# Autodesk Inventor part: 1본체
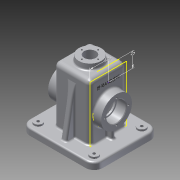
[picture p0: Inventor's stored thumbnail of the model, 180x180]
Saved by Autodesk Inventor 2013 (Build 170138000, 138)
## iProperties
Created: 2016-01
Part Number: 1본체
Material: 알루미늄 6061
Document SubType Name: Modeling
Designer: Administrator
Density: 2.71 g/cm^3
Mass: 927.953 g
Surface Area: 977.096 cm^2
Volume: 342.418 cm^3
Author: Administrator
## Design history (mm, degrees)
sketch "스케치1"
  geometry: L1 (32.5, -32.5)-(-32.5, -32.5); L2 (-32.5, -32.5)-(-32.5, 32.5); L3 (-32.5, 32.5)-(32.5, 32.5); L4 (32.5, 32.5)-(32.5, -32.5); L5 (32.5, -32.5)-(-32.5, 32.5); L6 (-32.5, -32.5)-(32.5, 32.5); 1 further point
  constraints: 12 end point, 2 midpoint, 2 parallel, 1 horizontal, 1 perpendicular
  dimensions: "d0" = 65 distance of L2.end L3.end; "d2" = 65 distance of L1.end L2.end
extrude "돌출1" new body sketch "스케치1" distance "d3" = 110; taper "d4" = 0 deg
feature "쉘1" dims "d5" = 5
sketch "스케치3"
  geometry: L1 (0, 65)-(0, 0) reference; C1 r 27.5 at (-55, 32.5); 2 further points
  constraints: 1 centre point, 1 horizontal alignment, 1 midpoint
  dimensions: "d6" = 55 diameter of C1; "d7" = 55 distance of point (0, 32.5) C1.centre
extrude "돌출2" join sketch "스케치3" distance "d8" = 15; taper "d9" = 0 deg
hole "구멍1" diameter "d12" = 30; stored, may be unused: countersink angle "d16" = 90 deg, drill point angle "d18" = 0 deg; dims "d10" = 10, "d11" = 10, "d13" = 6, "d14" = 35, "d15" = 17, "d17" = 8
sketch "스케치4"
  geometry: C1 r 17.5 at (0, 0) reference; 2 further points
  constraints: 1 horizontal alignment
  dimensions: "d19" = 21 distance of C1.centre point (-21, 0)
hole "구멍2" sketch "스케치4" at (-21, 0) diameter "d20" = 3.242; stored, may be unused: countersink angle "d24" = 90 deg, drill point angle "d26" = 118 deg; dims "d21" = 8, "d22" = 35, "d23" = 17, "d25" = 10
node "작업 평면1"
sketch "스케치5"
  geometry: C1 r 20 at (0, 0); 1 further point
  constraints: 1 centre point, 1 coincident
  dimensions: "d31" = 40 diameter of C1
extrude "돌출3" join sketch "스케치5" stored distance "d32" = 15; taper "d33" = 5 deg
sketch "스케치6"
  geometry: C1 r 20 at (0, 0) reference; C2 r 10.5 at (0, 0)
  constraints: 1 centre point, 1 coincident
  dimensions: "d34" = 21 diameter of C2
extrude "돌출4" cut sketch "스케치6" stored distance "d35" = 15; taper "d36" = 0 deg
sketch "스케치7"
  geometry: C1 r 10.5 at (0, 0) reference; 1 further point
  constraints: 1 horizontal alignment
  dimensions: "d37" = 14.5 distance of point (14.5, 0) C1.centre
hole "구멍3" sketch "스케치7" at (14.5, 0) diameter "d38" = 2.459; stored, may be unused: countersink angle "d42" = 90 deg, drill point angle "d44" = 118 deg; dims "d39" = 7, "d40" = 35, "d41" = 17, "d43" = 9
sketch "스케치8"
  geometry: L1 (-65, 57.5)-(65, 57.5); L2 (65, 57.5)-(65, -57.5); L3 (65, -57.5)-(-65, -57.5); L4 (-65, -57.5)-(-65, 57.5); L5 (-65, 57.5)-(65, -57.5); L6 (65, 57.5)-(-65, -57.5); 1 further point
  constraints: 12 end point, 2 midpoint, 2 parallel, 1 horizontal, 1 perpendicular
  dimensions: "d48" = 130 distance of L1.start L1.end; "d50" = 115 distance of L1.end L2.end
extrude "돌출5" join sketch "스케치8" distance "d51" = 10; taper "d52" = 0 deg
fillet "모깎기1" dims "d53" = 15
sketch "스케치10"
  geometry: C1 r 7.5 at (-50, 42.5); C2 r 7.5 at (50, 42.5); C3 r 7.5 at (50, -42.5); C4 r 7.5 at (-50, -42.5); A1 r 15 centre (50, -42.5) between (50, -57.5) and (65, -42.5) reference; A2 r 15 centre (50, 42.5) between (65, 42.5) and (50, 57.5) reference; A3 r 15 centre (-50, 42.5) between (-50, 57.5) and (-65, 42.5) reference; A4 r 15 centre (-50, -42.5) between (-65, -42.5) and (-50, -57.5) reference; 1 further point
  constraints: 4 centre point, 4 coincident
  dimensions: "d54" = 15 diameter of C1; "d55" = 15 diameter of C2; "d56" = 15 diameter of C3; "d57" = 15 diameter of C4
extrude "돌출6" join sketch "스케치10" distance "d58" = 3; taper "d59" = 0 deg
sketch "스케치11"
  geometry: L1 (-50, -57.5)-(50, -57.5) reference; L2 (65, -42.5)-(65, 42.5) reference; L3 (50, 57.5)-(-50, 57.5) reference; L4 (-65, 42.5)-(-65, -42.5) reference; L5 (50, -52.5)-(-50, -52.5); L6 (-60, -42.5)-(-60, 42.5); L7 (-50, 52.5)-(50, 52.5); L8 (60, 42.5)-(60, -42.5); A1 r 15 centre (-50, -42.5) between (-65, -42.5) and (-50, -57.5) reference; A2 r 15 centre (50, -42.5) between (50, -57.5) and (65, -42.5) reference; A3 r 15 centre (50, 42.5) between (65, 42.5) and (50, 57.5) reference; A4 r 15 centre (-50, 42.5) between (-50, 57.5) and (-65, 42.5) reference; A5 r 10 centre (-50, -42.5) between (-60, -42.5) and (-50, -52.5); A6 r 10 centre (-50, 42.5) between (-50, 52.5) and (-60, 42.5); A7 r 10 centre (50, 42.5) between (60, 42.5) and (50, 52.5); A8 r 10 centre (50, -42.5) between (50, -52.5) and (60, -42.5); 1 further point
  constraints: 8 end point, 8 point on circle, 4 centre point, 7 other
  dimensions: "d60" = 5 distance between parallel lines of L5 L1
extrude "돌출7" join sketch "스케치11" distance "d62" = 2; taper "d63" = 0 deg
sketch "스케치12"
  geometry: A1 r 10 centre (-50, -42.5) between (-60, -42.5) and (-50, -52.5) reference; A2 r 10 centre (50, -42.5) between (50, -52.5) and (60, -42.5) reference; A3 r 10 centre (50, 42.5) between (60, 42.5) and (50, 52.5) reference; A4 r 10 centre (-50, 42.5) between (-50, 52.5) and (-60, 42.5) reference; 1 further point
hole "구멍4" sketch "스케치12" at (50, -42.5), (-50, -42.5), (-50, 42.5), (50, 42.5) diameter "d64" = 5; stored, may be unused: countersink angle "d68" = 90 deg, drill point angle "d70" = 118 deg; dims "d65" = 7, "d66" = 35, "d67" = 17, "d69" = 9
sketch "스케치17"
  geometry: L1 (32.5, 82.5)-(47.5, 82.5) reference; L2 (47.5, 82.5)-(47.5, 77.621) reference; L3 (47.5, 77.621)-(37.5, 77.621) reference; L4 (37.5, 77.621)-(36.526, 76) reference; L5 (36.526, 76)-(37.5, 74.379) reference; L6 (37.5, 74.379)-(47.5, 74.379) reference; L7 (47.5, 74.379)-(47.5, 72.5) reference; L8 (47.5, 72.5)-(30.5, 72.5) reference; L9 (30.5, 72.5)-(30.5, 70) reference; L10 (30.5, 70)-(27.5, 70) reference; L11 (27.5, 70)-(27.5, 105) reference; L12 (27.5, 105)-(10.5, 105) reference; L13 (10.5, 105)-(10.5, 120) reference; L14 (10.5, 120)-(13.271, 120) reference; L15 (13.271, 120)-(13.271, 111) reference; L16 (13.271, 111)-(14.5, 110.261) reference; L17 (14.5, 110.261)-(15.73, 111) reference; L18 (15.73, 111)-(15.73, 120) reference; L19 (15.73, 120)-(20, 120) reference; L20 (20, 120)-(20.875, 110) reference; L21 (20.875, 110)-(32.5, 110) reference; L22 (32.5, 110)-(32.5, 82.5) reference; L23 (-36.526, 34)-(-37.5, 35.621) reference; L24 (-37.5, 35.621)-(-47.5, 35.621) reference; L25 (-47.5, 35.621)-(-47.5, 37.5) reference; L26 (-47.5, 37.5)-(-30.5, 37.5) reference; L27 (-30.5, 37.5)-(-30.5, 40) reference; L28 (-30.5, 40)-(-27.5, 40) reference; L29 (-27.5, 40)-(-27.5, 10) reference; L30 (-27.5, 10)-(27.5, 10) reference; L31 (27.5, 10)-(27.5, 40) reference; L32 (27.5, 40)-(30.5, 40) reference; L33 (30.5, 40)-(30.5, 37.5) reference; L34 (30.5, 37.5)-(47.5, 37.5) reference; L35 (47.5, 37.5)-(47.5, 35.621) reference; L36 (47.5, 35.621)-(37.5, 35.621) reference; L37 (37.5, 35.621)-(36.526, 34) reference; L38 (36.526, 34)-(37.5, 32.379) reference; L39 (37.5, 32.379)-(47.5, 32.379) reference; L40 (47.5, 32.379)-(47.5, 27.5) reference; L41 (47.5, 27.5)-(32.5, 27.5) reference; L42 (32.5, 27.5)-(32.5, 10) reference; L43 (32.5, 10)-(65, 10) reference; L44 (65, 10)-(65, -2) reference; L45 (-65, -2)-(-65, 10) reference; L46 (-65, 10)-(-32.5, 10) reference; L47 (-32.5, 10)-(-32.5, 27.5) reference; L48 (-32.5, 27.5)-(-47.5, 27.5) reference; L49 (-47.5, 27.5)-(-47.5, 32.379) reference; L50 (-47.5, 32.379)-(-37.5, 32.379) reference; L51 (-37.5, 32.379)-(-36.526, 34) reference; L52 (-37.5, 74.379)-(-36.526, 76) reference; L53 (-36.526, 76)-(-37.5, 77.621) reference; L54 (-37.5, 77.621)-(-47.5, 77.621) reference; L55 (-47.5, 77.621)-(-47.5, 82.5) reference; L56 (-47.5, 82.5)-(-32.5, 82.5) reference; L57 (-32.5, 82.5)-(-32.5, 110) reference; L58 (-32.5, 110)-(-20.875, 110) reference; L59 (-20.875, 110)-(-20, 120) reference; L60 (-20, 120)-(-15.73, 120) reference; L61 (-15.73, 120)-(-15.73, 111) reference; L62 (-15.73, 111)-(-14.5, 110.261) reference; L63 (-14.5, 110.261)-(-13.271, 111) reference; L64 (-13.271, 111)-(-13.271, 120) reference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; 1 further point
  constraints: 8 end point, 2 parallel, 1 horizontal, 1 perpendicular
  dimensions: "d106" = 10 distance of L42.end L74.end; "d107" = 4 distance between parallel lines of L41 L76
extrude "돌출10" join sketch "스케치17" stored distance "d108" = 6; taper "d109" = 0 deg
sketch "스케치14"
  geometry: L1 (-20.875, 110)-(-20, 120) reference; L2 (-20, 120)-(-15.73, 120) reference; L3 (-15.73, 120)-(-15.73, 111) reference; L4 (-15.73, 111)-(-14.5, 110.261) reference; L5 (-14.5, 110.261)-(-13.271, 111) reference; L6 (-13.271, 111)-(-13.271, 120) reference; L7 (-13.271, 120)-(-10.5, 120) reference; L8 (-10.5, 120)-(-10.5, 105) reference; L9 (-10.5, 105)-(-27.5, 105) reference; L10 (-27.5, 105)-(-27.5, 10) reference; L11 (-27.5, 10)-(27.5, 10) reference; L12 (27.5, 10)-(27.5, 105) reference; L13 (27.5, 105)-(10.5, 105) reference; L14 (10.5, 105)-(10.5, 120) reference; L15 (10.5, 120)-(13.271, 120) reference; L16 (13.271, 120)-(13.271, 111) reference; L17 (13.271, 111)-(14.5, 110.261) reference; L18 (14.5, 110.261)-(15.73, 111) reference; L19 (15.73, 111)-(15.73, 120) reference; L20 (15.73, 120)-(20, 120) reference; L21 (20, 120)-(20.875, 110) reference; L22 (20.875, 110)-(32.5, 110) reference; L23 (32.5, 110)-(32.5, 10) reference; L24 (32.5, 10)-(57.5, 10) reference; L25 (57.5, 10)-(57.5, -2) reference; L26 (-57.5, -2)-(-57.5, 10) reference; L27 (-57.5, 10)-(-32.5, 10) reference; L28 (-32.5, 10)-(-32.5, 110) reference; L29 (-32.5, 110)-(-20.875, 110) reference; L30 (-57.5, 10)-(-42.5, 10) reference; L31 (-32.5, 95.069)-(-47.5, 10); L32 (57.5, -2)-(52.5, -2) reference; L33 (52.5, -2)-(52.5, 0) reference; L34 (52.5, 0)-(-52.5, 0) reference; L35 (-52.5, 0)-(-52.5, -2) reference; L36 (-52.5, -2)-(-57.5, -2) reference; 1 further point
  constraints: 2 end point, 2 point on line
  dimensions: "d79" = 10 distance of L26.end L31.end; "d80" = 10 deg angle of L26 L31
feature "리브1" sketch "스케치14" dims "d81" = 1, "d82" = 10, "d83" = 0, "d84" = 0, "d85" = 1, "d86" = 1
sketch "스케치15"
  geometry: L1 (100, 0)-(100, 65) reference; L2 (100, 65)-(0, 65) reference; L3 (0, 0)-(0, 65) reference; L4 (100, 0)-(0, 0) reference; L5 (100, 0)-(100, 65) reference; L6 (82.5, 29.5)-(82.5, 32.5) reference; L7 (82.5, 32.5)-(82.5, 35.5) reference; L8 (-10, 12.5)-(-10, 52.5) reference; A1 r 27.5 centre (55, 32.5) between (82.5, 32.5) and (82.5, 32.5) reference; 5 further points; 2 other entities
  constraints: 3 other
  dimensions: "d87" = 32.5 distance from line of point (17, 32.5) L4; "d88" = 27 distance from line of L8 point (17, 32.5)
fillet "모깎기2" dims "d89" = 8
fillet "모깎기3" dims "d90" = 8
chamfer "모따기1" distance "d93" = 1; stored, may be unused: second distance "d94" = 2, angle "d95" = 45 deg
fillet "모깎기6" dims "d96" = 0.3
fillet "모깎기7" dims "d97" = 3
fillet "모깎기8" dims "d98" = 3
fillet "모깎기10" dims "d110" = 3
fillet "모깎기11" dims "d111" = 3
sketch "스케치18"
  geometry: L1 (27.5, 27.5)-(-27.5, 27.5); L2 (-27.5, 27.5)-(-27.5, -27.5); L3 (-27.5, -27.5)-(27.5, -27.5); L4 (27.5, -27.5)-(27.5, 27.5); L5 (27.5, 27.5)-(-27.5, -27.5); L6 (-27.5, 27.5)-(27.5, -27.5); 1 further point
  constraints: 12 end point, 2 midpoint, 2 parallel, 1 horizontal, 1 perpendicular
  dimensions: "d114" = 55 distance of L2.end L3.end; "d116" = 55 distance of L1.end L2.end
extrude "돌출11" cut sketch "스케치18" stored distance "d117" = 6; taper "d118" = 0 deg
fillet "모깎기14" dims "d119" = 3
fillet "모깎기15" dims "d120" = 3
fillet "모깎기9" dims "d99" = 3
node "솔리드1"
pattern_circular "원형 패턴1" dims angle "d28" = 360 deg
mirror "대칭1"
pattern_circular "원형 패턴2" dims angle "d46" = 360 deg
mirror "대칭2"
mirror "대칭3"
node "절단 모서리 투영2"
node "절단 모서리 투영4"
